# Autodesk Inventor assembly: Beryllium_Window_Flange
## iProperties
Shininess: 64.0
Length Units: 11269
Angle Units: 11279
Time Units: 11290
Mass Units: 11283
Length Display Precision: 3
Angle Display Precision: 2
Compacted: True
Created: 2004-07
Part Number: Beryllium_Window_Flange
Document SubType Name: Assembly
Designer: John Blackburn
Manufacturer: Standard
Standards Organization: Custom
Density: 0.0
Volumn: 0.0
Area: 0.0
PropertySet Name: Model Information
Control State: 0
Master: False
Checked Out: False
Author: John Blackburn
